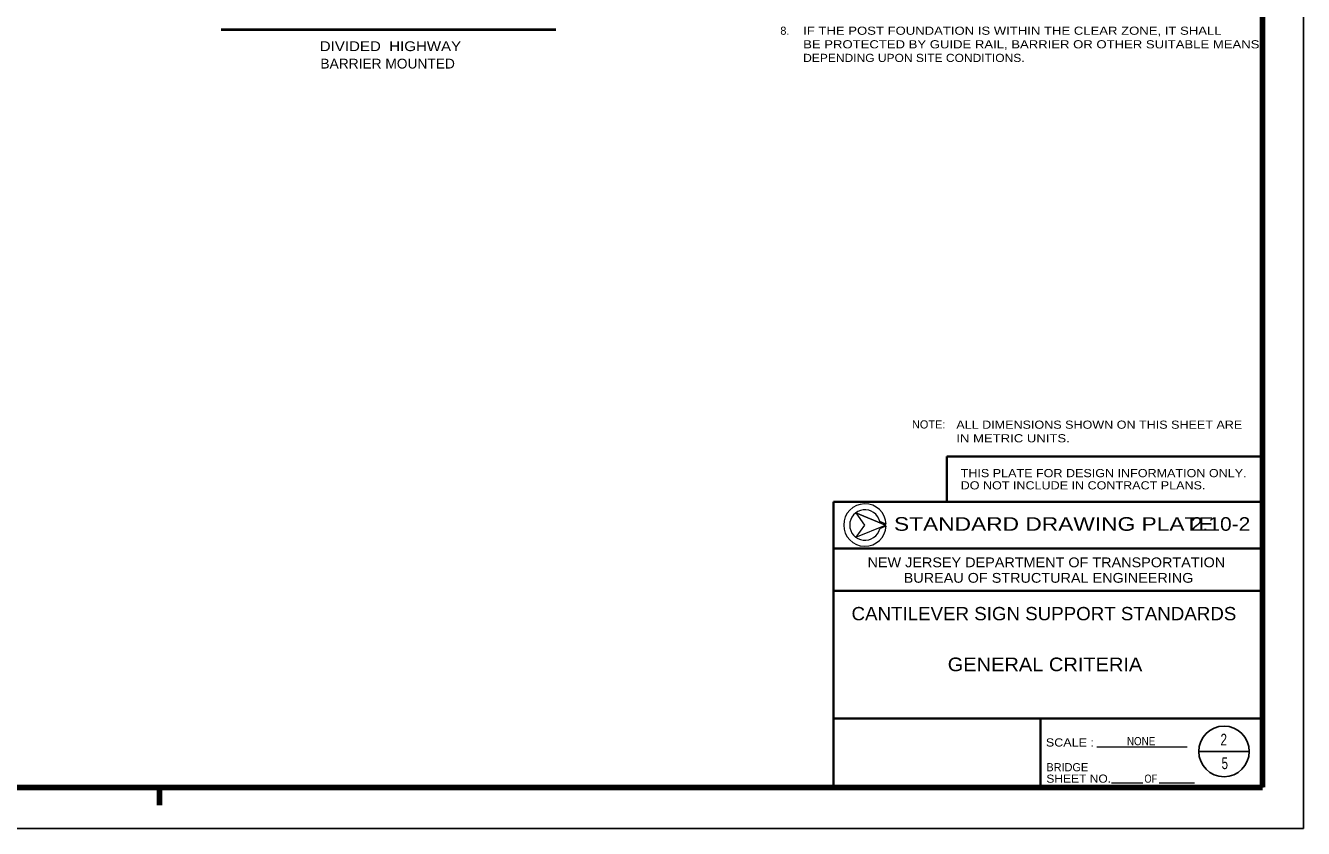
# Model space of a CAD drawing. Extents: x 312601.858 to 312602.699, y 144420.109 to 144420.704.
# Drawn here: x 312602.229 to 312602.6988, y 144420.1095 to 144420.4046 of the extents above; entities that cross this region are included whole.
import ezdxf
from ezdxf.enums import TextEntityAlignment as Align

# ---------------------------------------------------------------- set-up
doc = ezdxf.new("R2010")
doc.units = 0
doc.header["$LTSCALE"] = 0.0012
doc.layers.add('1', color=7, linetype='Continuous', lineweight=13)
doc.layers.add('39', color=7, linetype='Continuous', lineweight=13)
for name, color, linetype in [('2', 7, 'Continuous'), ('4', 7, 'Continuous'), ('51', 7, 'Continuous')]:
    doc.layers.add(name, color=color, linetype=linetype)

msp = doc.modelspace()

# ---------------------------------------------------------------- linework, layer by layer
at = {"layer": '1'}
for p, q in [((312602.5431, 144420.2197), (312602.5454, 144420.2207)), ((312602.5431, 144420.2197), (312602.5454, 144420.2207)), ((312602.6283, 144420.1263), (312602.6398, 144420.1263)), ((312602.6286, 144420.1263), (312602.6392, 144420.1263)), ((312602.6458, 144420.1263), (312602.6573, 144420.1263)), ((312602.6459, 144420.1263), (312602.6587, 144420.1263))]:
    msp.add_line(p, q, dxfattribs=at)
at = {"layer": '1', "lineweight": 25}
msp.add_lwpolyline([(312601.8578, 144420.1095), (312602.6988, 144420.1095), (312602.6988, 144420.7035)], dxfattribs=at)
at = {"layer": '1'}
for points in [[(312602.5452, 144420.221), (312602.5343, 144420.2255), (312602.5452, 144420.221)], [(312602.5452, 144420.221), (312602.5343, 144420.2255), (312602.5452, 144420.221)], [(312602.5454, 144420.2213), (312602.5431, 144420.2223), (312602.543, 144420.2223)], [(312602.5454, 144420.2213), (312602.5431, 144420.2223), (312602.543, 144420.2223)]]:
    msp.add_lwpolyline(points, dxfattribs=at)
for points in [[(312602.5452, 144420.221), (312602.5343, 144420.2255), (312602.5375, 144420.221), (312602.5343, 144420.2165)], [(312602.5375, 144420.221), (312602.5343, 144420.2165), (312602.5452, 144420.221), (312602.5343, 144420.2255)], [(312602.5452, 144420.221), (312602.5343, 144420.2255), (312602.5375, 144420.221), (312602.5343, 144420.2165)], [(312602.5375, 144420.221), (312602.5343, 144420.2165), (312602.5452, 144420.221), (312602.5343, 144420.2255)]]:
    msp.add_lwpolyline(points, close=True, dxfattribs=at)
for radius, start, end in [(0.0078026, 2.21392, 357.78608), (0.0078026, 2.21392, 357.78608), (0.0056, 13.69411, 346.30589), (0.0056, 13.69411, 346.30589)]:
    msp.add_arc((312602.5376, 144420.221), radius, start, end, dxfattribs=at)
at = {"layer": '39', "lineweight": 25}
for p, q in [((312602.6988, 144420.1095), (312602.6988, 144420.7035)), ((312602.6789, 144420.1378), (312602.6603, 144420.1378)), ((312602.6789, 144420.1378), (312602.6603, 144420.1378)), ((312602.452, 144420.1245), (312602.6838, 144420.1245)), ((312602.452, 144420.1245), (312602.6838, 144420.1245)), ((312602.452, 144420.1245), (312602.6838, 144420.1245))]:
    msp.add_line(p, q, dxfattribs=at)
at = {"layer": '39', "lineweight": 158}
for p, q in [((312602.6838, 144420.1247), (312602.6838, 144420.6645)), ((312601.9088, 144420.1245), (312602.6838, 144420.1245)), ((312602.2783, 144420.1181), (312602.2783, 144420.1245))]:
    msp.add_line(p, q, dxfattribs=at)
at = {"layer": '39', "lineweight": 40}
msp.add_line((312602.3009, 144420.4031), (312602.424, 144420.4031), dxfattribs=at)
at = {"layer": '39', "lineweight": 35}
for p, q in [((312602.5677, 144420.2462), (312602.6838, 144420.2462)), ((312602.5677, 144420.2295), (312602.5677, 144420.2462)), ((312602.5677, 144420.2462), (312602.6838, 144420.2462)), ((312602.5677, 144420.2295), (312602.5677, 144420.2462)), ((312602.526, 144420.1245), (312602.526, 144420.2295)), ((312602.526, 144420.2295), (312602.6838, 144420.2295)), ((312602.526, 144420.1245), (312602.526, 144420.2295)), ((312602.6838, 144420.2295), (312602.6838, 144420.1245)), ((312602.6838, 144420.2295), (312602.6838, 144420.1245)), ((312602.6838, 144420.2295), (312602.6838, 144420.1245)), ((312602.526, 144420.2124), (312602.6838, 144420.2124)), ((312602.526, 144420.1968), (312602.6838, 144420.1968)), ((312602.526, 144420.1499), (312602.6838, 144420.1499)), ((312602.526, 144420.1499), (312602.6838, 144420.1499)), ((312602.6022, 144420.1248), (312602.6022, 144420.1499)), ((312602.6022, 144420.1248), (312602.6022, 144420.1499))]:
    msp.add_line(p, q, dxfattribs=at)
at = {"layer": '39'}
for p, q in [((312602.6022, 144420.1499), (312602.6838, 144420.1499)), ((312602.6022, 144420.1499), (312602.6838, 144420.1499)), ((312602.6229, 144420.1395), (312602.6561, 144420.1395)), ((312602.6229, 144420.1395), (312602.6561, 144420.1395))]:
    msp.add_line(p, q, dxfattribs=at)
msp.add_lwpolyline([(312602.5452, 144420.221), (312602.5343, 144420.2255), (312602.5375, 144420.221), (312602.5343, 144420.2165)], close=True, dxfattribs=at)
msp.add_lwpolyline([(312602.5452, 144420.221), (312602.5343, 144420.2255), (312602.5375, 144420.221), (312602.5343, 144420.2165)], close=True, dxfattribs=at)
at = {"layer": '39', "lineweight": 25}
msp.add_circle((312602.6696, 144420.1378), 0.0093005, dxfattribs=at)
msp.add_circle((312602.6696, 144420.1378), 0.0093005, dxfattribs=at)

# ---------------------------------------------------------------- texts
at = {"layer": '1'}
msp.add_text('8.', height=0.003, dxfattribs=at).set_placement((312602.5065, 144420.4012))
at = {"layer": '1', "width": 1.05}
msp.add_text('BARRIER MOUNTED', height=0.0036, dxfattribs=at).set_placement((312602.36215, 144420.3888), align=Align.CENTER)
at = {"layer": '1', "width": 0.9}
msp.add_text('NONE', height=0.003, dxfattribs=at).set_placement((312602.6339, 144420.1401))
at = {"layer": '2', "width": 1.15}
for s, p in [('THIS PLATE FOR DESIGN INFORMATION ONLY.', (312602.5728, 144420.2386)), ('THIS PLATE FOR DESIGN INFORMATION ONLY.', (312602.5728, 144420.2386)), ('DO NOT INCLUDE IN CONTRACT PLANS.', (312602.5728, 144420.2341)), ('DO NOT INCLUDE IN CONTRACT PLANS.', (312602.5728, 144420.2341))]:
    msp.add_text(s, height=0.003, dxfattribs=at).set_placement(p)
at = {"layer": '2'}
for s, height, width, p in [('2.10-2', 0.005, 1.15, (312602.66835, 144420.2189)), ('CANTILEVER SIGN SUPPORT STANDARDS', 0.0049, 1.05, (312602.6034, 144420.186)), ('GENERAL CRITERIA', 0.005, 1.1, (312602.6038, 144420.1673))]:
    msp.add_text(s, height=height, dxfattribs=dict(at, width=width)).set_placement(p, align=Align.CENTER)
at = {"layer": '39'}
for s, width, p in [('IF THE POST FOUNDATION IS WITHIN THE CLEAR ZONE, IT SHALL', 1.2, (312602.5149, 144420.4012)), ('BE PROTECTED BY GUIDE RAIL, BARRIER OR OTHER SUITABLE MEANS, ', 1.2, (312602.5149, 144420.3962)), ('DEPENDING UPON SITE CONDITIONS.', 1.1, (312602.5149, 144420.3912)), ('SHEET NO.', 1.1, (312602.6043, 144420.1263)), ('SHEET NO.', 1.1, (312602.6043, 144420.1263))]:
    msp.add_text(s, height=0.003, dxfattribs=dict(at, width=width)).set_placement(p)
for s, height, width, p in [('DIVIDED  HIGHWAY ', 0.0036, 1.15, (312602.36395, 144420.3952)), ('STANDARD DRAWING PLATE       ', 0.005, 1.25, (312602.61515, 144420.2189)), ('NEW JERSEY DEPARTMENT OF TRANSPORTATION', 0.003599, 1.1, (312602.6043, 144420.2055)), ('BUREAU OF STRUCTURAL ENGINEERING', 0.0036, 1.1, (312602.6051, 144420.1998)), ('SCALE :', 0.003, 1.15, (312602.61295, 144420.1396)), ('SCALE :', 0.003, 1.15, (312602.61295, 144420.1396)), ('OF', 0.003, 0.85, (312602.6427, 144420.1263)), ('OF', 0.003, 0.85, (312602.6427, 144420.1263))]:
    msp.add_text(s, height=height, dxfattribs=dict(at, width=width)).set_placement(p, align=Align.CENTER)
msp.add_text('BRIDGE', height=0.003, dxfattribs=at).set_placement((312602.6043, 144420.1305))
msp.add_text('BRIDGE', height=0.003, dxfattribs=at).set_placement((312602.6043, 144420.1305))
at = {"layer": '4'}
msp.add_text('NOTE:', height=0.003, dxfattribs=at).set_placement((312602.5549, 144420.2565))
for s, width, p in [('ALL DIMENSIONS SHOWN ON THIS SHEET ARE', 1.15, (312602.5712, 144420.2564)), ('IN METRIC UNITS.', 1.2, (312602.5712, 144420.2514))]:
    msp.add_text(s, height=0.003, dxfattribs=dict(at, width=width)).set_placement(p)
at = {"layer": '51', "width": 0.75}
for s, p in [('2', (312602.6695, 144420.14)), ('5', (312602.6699, 144420.1313))]:
    msp.add_text(s, height=0.0043, dxfattribs=at).set_placement(p, align=Align.CENTER)

doc.saveas('drawing.dxf')
